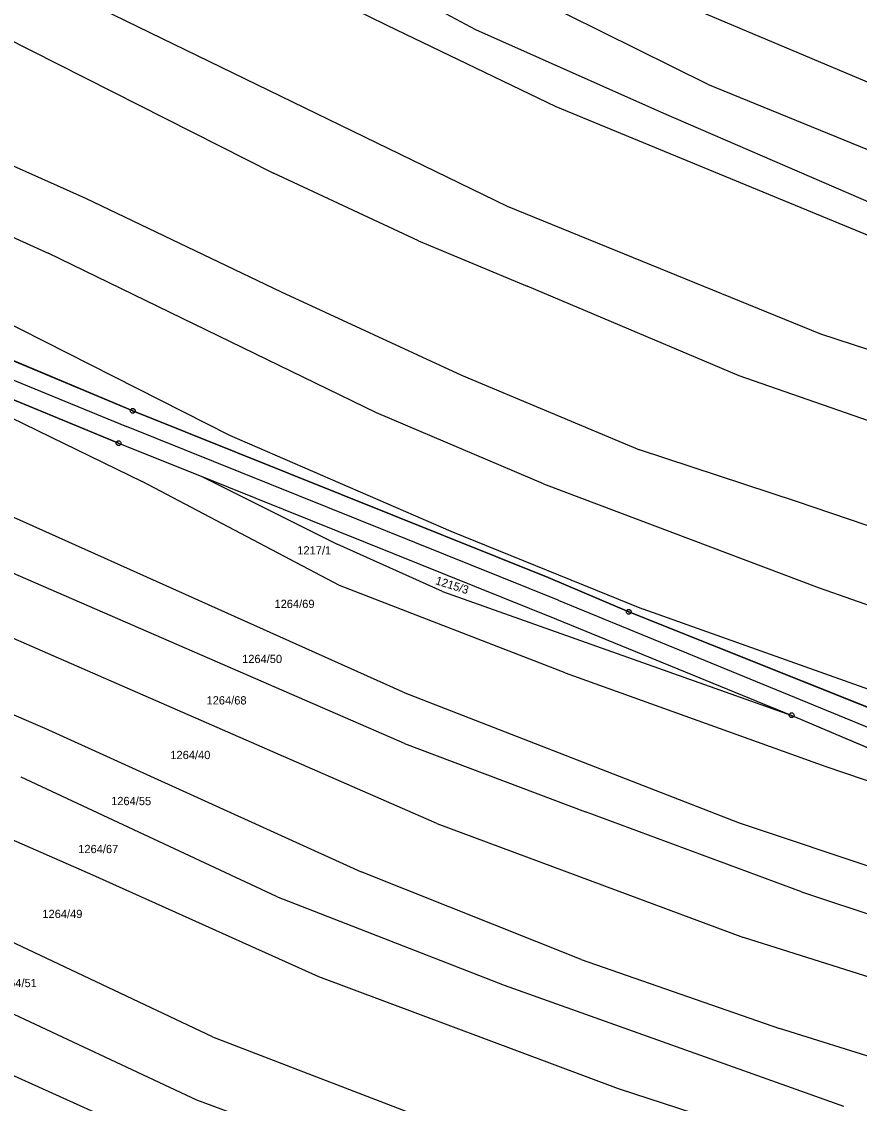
# Model space of a CAD drawing. Extents: x -777309 to -774195, y -1144706 to -1143600.
# Drawn here: x -776362 to -776190.1, y -1144266.5 to -1144044.3 of the extents above; entities that cross this region are included whole.
import ezdxf

# ---------------------------------------------------------------- set-up
doc = ezdxf.new("R2010")
doc.units = 0
for name, color, linetype in [('1', 7, 'Continuous'), ('11', 7, 'Continuous'), ('2', 7, 'Continuous'), ('6', 7, 'Continuous'), ('8', 7, 'Continuous')]:
    doc.layers.add(name, color=color, linetype=linetype)

msp = doc.modelspace()

# ---------------------------------------------------------------- linework, layer by layer
at = {"layer": '1'}
for p, q in [((-776221.27, -1144057.17), (-776344.1, -1143996.17)), ((-776351.09, -1144013.34), (-776287.1, -1144045.07)), ((-776311.69, -1144022.93), (-776268.85, -1144045.98)), ((-776246.74, -1144031.99), (-776181.26, -1144059.74)), ((-776351.09, -1144039.08), (-776262.34, -1144082.22)), ((-776287.1, -1144045.07), (-776252.37, -1144061.74)), ((-776268.85, -1144045.98), (-776230.28, -1144063.14)), ((-776365.6, -1144047.46), (-776310.35, -1144075.44)), ((-776221.27, -1144057.17), (-776180.2, -1144074)), ((-776252.37, -1144061.74), (-776186.51, -1144088.97)), ((-776230.28, -1144063.14), (-776185.19, -1144082.67)), ((-776382.54, -1144065.64), (-776348.92, -1144080.63)), ((-776392.95, -1144075.37), (-776356.59, -1144091.91)), ((-776280.61, -1144089.36), (-776310.35, -1144075.44)), ((-776348.92, -1144080.63), (-776308.77, -1144099.81)), ((-776262.34, -1144082.22), (-776198.07, -1144108.44)), ((-776431.42, -1144085.55), (-776339.24, -1144124.31)), ((-776280.61, -1144089.36), (-776258.25, -1144098.68)), ((-776342.13, -1144130.92), (-776434.38, -1144092.81)), ((-776289.18, -1144124.7), (-776356.59, -1144091.91)), ((-776389.63, -1144093.66), (-776319.4, -1144129.31)), ((-776308.77, -1144099.81), (-776271.78, -1144116.96)), ((-776214.75, -1144117.12), (-776258.25, -1144098.68)), ((-776198.07, -1144108.44), (-776142.1, -1144126.74)), ((-776271.78, -1144116.96), (-776235.24, -1144132.31)), ((-776097.7, -1144157.79), (-776214.75, -1144117.12)), ((-776377.12, -1144119.5), (-776337.3, -1144138.78)), ((-776283.73, -1144182.09), (-776414.91, -1144123.19)), ((-776339.24, -1144124.31), (-776253.98, -1144158.55)), ((-776254.94, -1144139.28), (-776289.18, -1144124.7)), ((-776342.13, -1144130.92), (-776325.22, -1144137.73)), ((-776319.4, -1144129.31), (-776273.96, -1144148.97)), ((-776283.48, -1144192.64), (-776421.35, -1144132.65)), ((-776202.98, -1144142.91), (-776235.24, -1144132.31)), ((-776325.22, -1144137.73), (-776297.26, -1144151.64)), ((-776325.22, -1144137.73), (-776252.27, -1144167.08)), ((-776296.76, -1144160.19), (-776337.3, -1144138.78)), ((-776254.94, -1144139.28), (-776198.32, -1144160.66)), ((-776103.02, -1144176.77), (-776202.98, -1144142.91)), ((-776276.83, -1144209.03), (-776421.73, -1144145.66)), ((-776273.96, -1144148.97), (-776234.45, -1144165.02)), ((-776275.64, -1144161.42), (-776297.26, -1144151.64)), ((-776253.98, -1144158.55), (-776237.42, -1144165.58)), ((-776250.47, -1144178.1), (-776296.76, -1144160.19)), ((-776275.64, -1144161.42), (-776203.96, -1144186.83)), ((-776198.32, -1144160.66), (-776146.7, -1144178.71)), ((-776416.15, -1144164.19), (-776357.31, -1144189.49)), ((-776237.42, -1144165.58), (-776113.15, -1144215.23)), ((-776145.81, -1144196.56), (-776234.45, -1144165.02)), ((-776252.27, -1144167.08), (-776203.96, -1144186.83)), ((-776446.62, -1144176.16), (-776347.51, -1144219.6)), ((-776250.47, -1144178.1), (-776196.94, -1144197.35)), ((-776283.73, -1144182.09), (-776214.73, -1144208.93)), ((-776203.96, -1144186.83), (-776126.28, -1144219.86)), ((-776357.31, -1144189.49), (-776292.36, -1144218.98)), ((-776283.48, -1144192.64), (-776246.29, -1144206.67)), ((-776196.94, -1144197.35), (-776161.72, -1144209.31)), ((-776309.74, -1144224.06), (-776362.11, -1144199.54)), ((-776201.94, -1144223.07), (-776246.29, -1144206.67)), ((-776214.73, -1144208.93), (-776159.55, -1144227.35)), ((-776276.83, -1144209.03), (-776213.85, -1144232.45)), ((-776433.78, -1144215.31), (-776326.16, -1144265.8)), ((-776322.84, -1144252.89), (-776393.41, -1144219.56)), ((-776347.51, -1144219.6), (-776301.12, -1144240.48)), ((-776247.15, -1144237), (-776292.36, -1144218.98)), ((-776309.74, -1144224.06), (-776263.02, -1144242.23)), ((-776201.94, -1144223.07), (-776173.05, -1144232.7)), ((-776118.46, -1144262.59), (-776213.85, -1144232.45)), ((-776247.15, -1144237), (-776206.49, -1144251.17)), ((-776301.12, -1144240.48), (-776239.59, -1144263.48)), ((-776263.02, -1144242.23), (-776193.31, -1144267.08)), ((-776124.24, -1144276.84), (-776206.49, -1144251.17)), ((-776322.84, -1144252.89), (-776249.8, -1144280.91)), ((-776324.6, -1144278.51), (-776377.44, -1144254.65)), ((-776239.59, -1144263.48), (-776193.18, -1144278.57)), ((-776326.16, -1144265.8), (-776260.62, -1144289.93))]:
    msp.add_line(p, q, dxfattribs=at)
at = {"layer": '11'}
for points in [[(-776712.36, -1143980.08), (-776627.91, -1144012.39), (-776609.89, -1144021.72), (-776606.85, -1144023.34), (-776604.66, -1144024.21), (-776527.2, -1144055.02), (-776434.38, -1144092.81), (-776342.13, -1144130.92), (-776325.22, -1144137.73), (-776252.27, -1144167.08), (-776203.96, -1144186.83), (-776126.28, -1144219.86), (-776111.41, -1144230.44), (-776110.38, -1144234.15), (-776110.12, -1144235.08), (-776108.97, -1144239.22), (-776110.54, -1144243.08), (-776113.8, -1144251.1), (-776118.46, -1144262.59), (-776124.24, -1144276.84)], [(-776113.15, -1144215.23), (-776237.42, -1144165.58), (-776253.98, -1144158.55), (-776339.24, -1144124.31), (-776431.42, -1144085.55)]]:
    msp.add_lwpolyline(points, dxfattribs=at)
at = {"layer": '6'}
for p, q in [((-776525.97, -1144051.14), (-776340.5, -1144127.52)), ((-776251.9, -1144163.17), (-776340.5, -1144127.52)), ((-776251.9, -1144163.17), (-776096.98, -1144226.78))]:
    msp.add_line(p, q, dxfattribs=at)
at = {"layer": '8'}
for p, q in [((-776339.36, -1144124.31), (-776339.12, -1144124.31)), ((-776342.25, -1144130.92), (-776342.01, -1144130.92)), ((-776237.54, -1144165.58), (-776237.3, -1144165.58)), ((-776204.08, -1144186.83), (-776203.84, -1144186.83))]:
    msp.add_line(p, q, dxfattribs=at)
for points in [[(-776339.09, -1144123.83), (-776338.84, -1144124.01), (-776338.74, -1144124.3), (-776338.84, -1144124.59), (-776339.09, -1144124.77), (-776339.4, -1144124.77), (-776339.65, -1144124.59), (-776339.75, -1144124.3), (-776339.65, -1144124.01), (-776339.4, -1144123.83)], [(-776341.98, -1144130.44), (-776341.73, -1144130.62), (-776341.63, -1144130.91), (-776341.73, -1144131.2), (-776341.98, -1144131.38), (-776342.29, -1144131.38), (-776342.54, -1144131.2), (-776342.64, -1144130.91), (-776342.54, -1144130.62), (-776342.29, -1144130.44)], [(-776237.27, -1144165.1), (-776237.02, -1144165.28), (-776236.92, -1144165.57), (-776237.02, -1144165.86), (-776237.27, -1144166.04), (-776237.58, -1144166.04), (-776237.83, -1144165.86), (-776237.93, -1144165.57), (-776237.83, -1144165.28), (-776237.58, -1144165.1)], [(-776203.81, -1144186.35), (-776203.56, -1144186.53), (-776203.46, -1144186.82), (-776203.56, -1144187.11), (-776203.81, -1144187.29), (-776204.12, -1144187.29), (-776204.37, -1144187.11), (-776204.47, -1144186.82), (-776204.37, -1144186.53), (-776204.12, -1144186.35)]]:
    msp.add_lwpolyline(points, close=True, dxfattribs=at)

# ---------------------------------------------------------------- texts
at = {"layer": '2'}
for s, p in [('1217/1', (-776305.45, -1144153.79)), ('1264/69', (-776310.14, -1144164.79)), ('1264/50', (-776316.79, -1144176.09)), ('1264/68', (-776324.09, -1144184.6)), ('1264/40', (-776331.52, -1144195.82)), ('1264/55', (-776343.68, -1144205.28)), ('1264/67', (-776350.43, -1144215.14)), ('1264/49', (-776357.79, -1144228.47)), ('1264/51', (-776367.14, -1144242.66))]:
    msp.add_text(s, height=1.7, dxfattribs=at).set_placement(p)
msp.add_text('1215/3', height=1.7, rotation=342.285, dxfattribs=at).set_placement((-776277.23, -1144159.85))

doc.saveas('drawing.dxf')
